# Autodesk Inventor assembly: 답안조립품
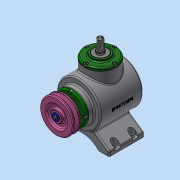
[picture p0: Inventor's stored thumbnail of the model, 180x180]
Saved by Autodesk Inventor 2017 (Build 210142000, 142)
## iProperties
Part Number: 답안조립품
Material: 일반
Document SubType Name: Assembly
Designer: MRC
Author: MRC
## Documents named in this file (17)
- C:\Users\MRC\Desktop\730108V1004\답안조립품.iam
- C:\Users\MRC\Desktop\730108V1004\본체.ipt
- C:\Users\MRC\Desktop\730108V1004\V-벨트풀리.ipt
- C:\Users\MRC\Desktop\730108V1004\메인 베벨기어.ipt
- C:\Users\MRC\Desktop\730108V1004\메인 축.ipt
- 메인 축.ipt
- C:\Users\MRC\Desktop\730108V1004\베어링 6203.ipt
- C:\Users\MRC\Desktop\730108V1004\볼트 M4 x 10.ipt
- C:\Users\MRC\Desktop\730108V1004\서브 베벨기어.ipt
- C:\Users\MRC\Desktop\730108V1004\서브 축.ipt
- 서브 축.ipt
- C:\Users\MRC\Desktop\730108V1004\오일실 17 x 32 x 8.ipt
- C:\Users\MRC\Desktop\730108V1004\와셔 4 x 16.ipt
- C:\Users\MRC\Desktop\730108V1004\육각볼트 M4 x 8.ipt
- C:\Users\MRC\Desktop\730108V1004\커버.ipt
- C:\Users\MRC\Desktop\730108V1004\키 4 x 4 x 14.ipt
- C:\Users\MRC\Desktop\730108V1004\키 5 x 5 x 14.ipt
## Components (1 placed, 1 different names)
1. V-벨트풀리:1
